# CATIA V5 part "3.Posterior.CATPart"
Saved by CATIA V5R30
Part number: 3.Posterior
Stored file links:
  C:\Users\valen\Desktop\Estandar CubeSat - Programa AVES-20220531T050024Z-001\Estandar CubeSat - Programa AVES\3D - MODELS\CATIA\3.Posterior.CATPart

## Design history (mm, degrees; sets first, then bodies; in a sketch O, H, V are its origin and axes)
Body1 "Solid1" (main body)
  Solid1: solid without history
